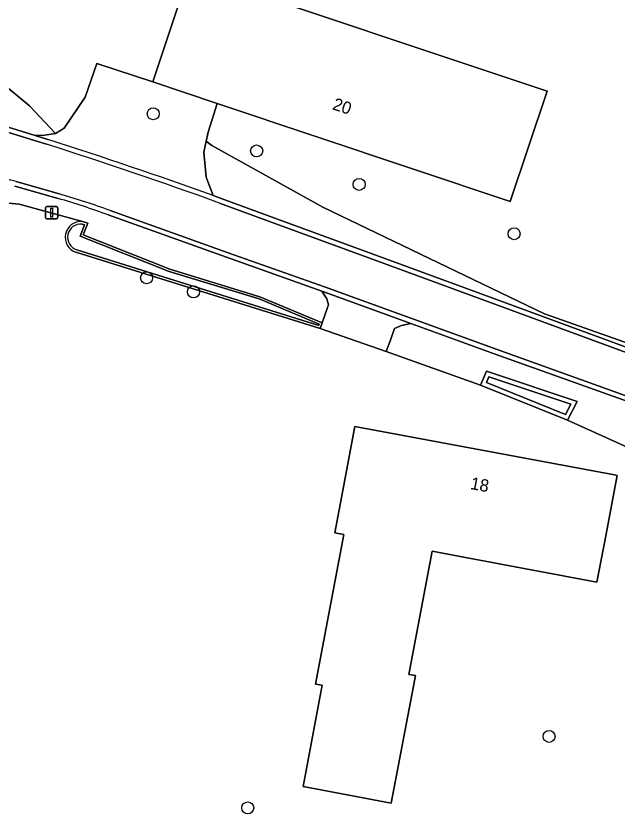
# Model space of a CAD drawing. Extents: x 162510 to 163918, y 388494 to 389774.
# Drawn here: x 162567.7 to 162616.6, y 389035.1 to 389100.2 of the extents above; entities that cross this region are included whole.
import ezdxf

# ---------------------------------------------------------------- set-up
doc = ezdxf.new("R2010")
doc.units = 0
for name, color, linetype in [('IMGEO_Berm_groen', 7, 'Continuous'), ('IMGEO_Boom', 7, 'Continuous'), ('IMGEO_Erf', 7, 'Continuous'), ('IMGEO_Groenvoorziening', 7, 'Continuous'), ('IMGEO_Oever', 7, 'Continuous'), ('IMGEO_Pand', 7, 'Continuous'), ('IMGEO_Pand_nummerreeks', 7, 'Continuous'), ('IMGEO_Rijbaan_lokaal_gesloten', 7, 'Continuous'), ('IMGEO_Rijbaan_lokaal_halfverhard', 7, 'Continuous'), ('IMGEO_Rijbaan_lokaal_open', 7, 'Continuous'), ('IMGEO_Verkeersbordpaal', 7, 'Continuous'), ('IMGEO_Voetpad_halfverhard', 7, 'Continuous'), ('IMGEO_Waterloop', 7, 'Continuous')]:
    doc.layers.add(name, color=color, linetype=linetype)

msp = doc.modelspace()

# ---------------------------------------------------------------- linework, layer by layer
at = {"layer": 'IMGEO_Berm_groen'}
for points in [[(162599.769, 389075.181), (162599.005, 389075.013), (162598.439, 389074.769), (162598.136, 389073.919), (162597.772, 389072.896), (162605.424, 389070.178), (162605.91, 389071.318), (162613.301, 389068.852), (162612.506, 389067.31), (162621.016, 389063.464), (162636.603, 389058.338), (162636.901, 389059.229), (162622.591, 389064.006)], [(162633.167, 389063.141), (162629.224, 389064.578), (162619.309, 389068.164), (162606.622, 389072.695), (162599.769, 389075.181)]]:
    msp.add_lwpolyline(points, dxfattribs=at)
at = {"layer": 'IMGEO_Boom'}
for centre in [(162578.829, 389092.237), (162587.236, 389089.214), (162595.566, 389086.496), (162608.163, 389082.483), (162578.292, 389078.903), (162582.101, 389077.76), (162611.002, 389041.609), (162586.511, 389035.793)]:
    msp.add_circle(centre, 0.489, dxfattribs=at)
at = {"layer": 'IMGEO_Erf'}
for points in [[(162557.496, 389100.727), (162561.475, 389097.699), (162566.874, 389094.459), (162568.765, 389092.878), (162570.879, 389090.626), (162571.596, 389091.063), (162573.303, 389093.589), (162574.241, 389096.331), (162578.784, 389094.826), (162581.781, 389103.795), (162610.841, 389094.076), (162607.844, 389085.107), (162584.039, 389093.069), (162583.288, 389090.735), (162583.138, 389090.012), (162583.595, 389089.671), (162592.606, 389084.643), (162610.637, 389075.969), (162619.919, 389072.683)], [(162573.072, 389083.47), (162567.934, 389084.89), (162565.92, 389085.075), (162565.003, 389085.162), (162560.951, 389085.473), (162557.784, 389085.129), (162557.523, 389080.69), (162560.632, 389000), (162561.923, 388970.136), (162563.311, 388929.674), (162563.923, 388911.946), (162569.898, 388915.03), (162570.179, 388926.053), (162598.167, 388927.269), (162614.582, 388927.982), (162666.94, 388930.257)], [(162677.463, 389048.046), (162644.844, 389055.627), (162639.858, 389057.267), (162636.603, 389058.338), (162621.016, 389063.464), (162612.506, 389067.31), (162605.424, 389070.178), (162597.772, 389072.896), (162592.401, 389074.784), (162572.538, 389080.978)]]:
    msp.add_lwpolyline(points, dxfattribs=at)
msp.add_lwpolyline([(162604.218, 389056.155), (162601.5, 389056.669), (162599.608, 389046.654), (162600.138, 389046.554), (162600.085, 389046.274), (162598.18, 389036.191), (162591.005, 389037.546), (162592.557, 389045.76), (162592.019, 389045.861), (162594.315, 389058.019), (162593.588, 389058.156), (162594.294, 389061.894), (162595.223, 389066.807), (162616.336, 389062.871), (162616.534, 389062.834), (162615.607, 389057.921), (162614.892, 389054.138)], close=True, dxfattribs=at)
msp.add_arc((162572.96, 389082.191), 1.284, 84.97508, 250.8354, dxfattribs=at)
at = {"layer": 'IMGEO_Groenvoorziening'}
for points in [[(162560.043, 389093.285), (162564.347, 389091.96), (162569.142, 389090.491), (162569.821, 389090.468), (162570.879, 389090.626), (162568.765, 389092.878), (162566.874, 389094.459), (162561.475, 389097.699)], [(162620.188, 389073.585), (162619.919, 389072.683), (162610.637, 389075.969), (162592.606, 389084.643), (162583.595, 389089.671), (162583.138, 389090.012), (162582.949, 389089.105), (162583.143, 389087.072), (162583.689, 389085.599), (162584.363, 389085.356), (162588.931, 389083.662), (162597.729, 389080.442), (162608.065, 389076.654), (162620.144, 389072.2), (162630.325, 389068.434)], [(162557.804, 389086.858), (162557.784, 389085.129), (162560.951, 389085.473), (162565.003, 389085.162), (162565.92, 389085.075), (162567.934, 389084.89), (162573.072, 389083.47), (162573.519, 389083.346), (162573.142, 389082.396), (162580.177, 389079.602), (162587.495, 389077.364), (162592.559, 389075.234), (162592.998, 389076.477), (162593.077, 389076.701), (162592.93, 389077.198), (162592.545, 389077.801), (162584.785, 389080.564), (162575.172, 389084.009)], [(162571.101, 389085.355), (162567.569, 389086.36)]]:
    msp.add_lwpolyline(points, dxfattribs=at)
msp.add_arc((162553.636, 389025.702), 62.157, 69.72791, 73.68109, dxfattribs=at)
at = {"layer": 'IMGEO_Oever'}
for points in [[(162573.045, 389083.274), (162573.256, 389083.215), (162572.887, 389082.286), (162580.112, 389079.417), (162587.428, 389077.179), (162592.313, 389075.125), (162592.279, 389075.028), (162572.607, 389081.162)], [(162580.177, 389079.602), (162573.142, 389082.396), (162573.519, 389083.346), (162573.072, 389083.47)], [(162572.538, 389080.978), (162592.401, 389074.784), (162592.559, 389075.234), (162587.495, 389077.364), (162580.177, 389079.602)]]:
    msp.add_lwpolyline(points, dxfattribs=at)
for points in [[(162605.91, 389071.318), (162605.424, 389070.178), (162612.506, 389067.31), (162613.301, 389068.852)], [(162606.12, 389070.852), (162612.766, 389068.634), (162612.329, 389067.787), (162605.92, 389070.383)]]:
    msp.add_lwpolyline(points, close=True, dxfattribs=at)
for centre, radius, start, end in [((162572.96, 389082.191), 1.284, 84.97508, 250.8354), ((162572.96, 389082.19), 1.087, 85.49441, 251.07303)]:
    msp.add_arc(centre, radius, start, end, dxfattribs=at)
at = {"layer": 'IMGEO_Pand'}
for points in [[(162578.784, 389094.826), (162584.039, 389093.069), (162607.844, 389085.107), (162610.841, 389094.076), (162581.781, 389103.795)], [(162604.218, 389056.155), (162614.892, 389054.138), (162615.607, 389057.921), (162616.534, 389062.834), (162616.336, 389062.871), (162595.223, 389066.807), (162594.294, 389061.894), (162593.588, 389058.156), (162594.315, 389058.019), (162592.019, 389045.861), (162592.557, 389045.76), (162591.005, 389037.546), (162598.18, 389036.191), (162600.085, 389046.274), (162600.138, 389046.554), (162599.608, 389046.654), (162601.5, 389056.669)]]:
    msp.add_lwpolyline(points, close=True, dxfattribs=at)
at = {"layer": 'IMGEO_Rijbaan_lokaal_gesloten'}
for points in [[(162570.141, 389089.767), (162564.229, 389091.578), (162559.938, 389092.899)], [(162567.675, 389086.732), (162571.175, 389085.726)], [(162630.186, 389068.059), (162619.847, 389071.883), (162607.927, 389076.278), (162597.591, 389080.066), (162588.792, 389083.287), (162584.227, 389084.98)], [(162575.34, 389084.366), (162584.931, 389080.923), (162592.748, 389078.167), (162606.773, 389073.076), (162619.448, 389068.517), (162629.327, 389064.949), (162633.3, 389063.513)]]:
    msp.add_lwpolyline(points, dxfattribs=at)
for centre, radius, start, end in [((162449.728, 388712.327), 396.182, 70.1543, 72.30597), ((162560.208, 389057.852), 29.83, 75.50391, 88.70383), ((162553.555, 389024.708), 63.511, 69.93984, 73.89327)]:
    msp.add_arc(centre, radius, start, end, dxfattribs=at)
at = {"layer": 'IMGEO_Rijbaan_lokaal_halfverhard'}
for points in [[(162570.258, 389090.149), (162569.142, 389090.491), (162564.347, 389091.96), (162560.043, 389093.285)], [(162559.938, 389092.899), (162564.229, 389091.578), (162570.141, 389089.767)], [(162571.175, 389085.726), (162567.675, 389086.732)], [(162567.569, 389086.36), (162571.101, 389085.355)], [(162630.325, 389068.434), (162620.144, 389072.2), (162608.065, 389076.654), (162597.729, 389080.442), (162588.931, 389083.662), (162584.363, 389085.356), (162583.689, 389085.599)], [(162584.227, 389084.98), (162588.792, 389083.287), (162597.591, 389080.066), (162607.927, 389076.278), (162619.847, 389071.883), (162630.186, 389068.059)], [(162575.172, 389084.009), (162584.785, 389080.564), (162592.545, 389077.801), (162592.692, 389077.749), (162599.769, 389075.181), (162606.622, 389072.695), (162619.309, 389068.164), (162629.224, 389064.578), (162633.167, 389063.141)], [(162633.3, 389063.513), (162629.327, 389064.949), (162619.448, 389068.517), (162606.773, 389073.076), (162592.748, 389078.167), (162584.931, 389080.923), (162575.34, 389084.366)]]:
    msp.add_lwpolyline(points, dxfattribs=at)
for centre, radius, start, end in [((162449.728, 388712.327), 396.182, 70.1543, 72.30597), ((162450.179, 388713.593), 395.238, 70.25732, 72.31315), ((162560.208, 389057.852), 29.83, 75.50391, 88.70383), ((162553.636, 389025.702), 62.157, 69.72791, 73.68109), ((162553.555, 389024.708), 63.511, 69.93984, 73.89327)]:
    msp.add_arc(centre, radius, start, end, dxfattribs=at)
at = {"layer": 'IMGEO_Rijbaan_lokaal_open'}
for points in [[(162583.288, 389090.735), (162584.039, 389093.069), (162578.784, 389094.826), (162574.241, 389096.331), (162573.303, 389093.589), (162571.596, 389091.063), (162570.879, 389090.626), (162569.821, 389090.468), (162569.142, 389090.491), (162570.258, 389090.149)], [(162583.689, 389085.599), (162583.143, 389087.072), (162582.949, 389089.105), (162583.138, 389090.012), (162583.288, 389090.735)]]:
    msp.add_lwpolyline(points, dxfattribs=at)
msp.add_arc((162450.179, 388713.593), 395.238, 70.25732, 72.31315, dxfattribs=at)
at = {"layer": 'IMGEO_Verkeersbordpaal'}
for p, q in [((162570.073, 389083.796), (162570.073, 389084.596)), ((162570.073, 389084.596), (162570.073, 389083.796)), ((162570.173, 389084.696), (162570.963, 389084.696)), ((162570.963, 389084.696), (162570.173, 389084.696)), ((162571.063, 389084.596), (162571.063, 389083.796)), ((162571.063, 389083.796), (162571.063, 389084.596)), ((162570.963, 389083.696), (162570.173, 389083.696)), ((162570.173, 389083.696), (162570.963, 389083.696))]:
    msp.add_line(p, q, dxfattribs=at)
msp.add_lwpolyline([(162570.493, 389084.571), (162570.643, 389084.571), (162570.643, 389083.821), (162570.493, 389083.821), (162570.493, 389084.571)], dxfattribs=at)
for centre, start, end in [((162570.173, 389084.596), 90, 180), ((162570.173, 389084.596), 90, 180), ((162570.963, 389084.596), 0, 90), ((162570.963, 389084.596), 360, 90), ((162570.173, 389083.796), 180, 270), ((162570.173, 389083.796), 180, 270), ((162570.963, 389083.796), 270, 0), ((162570.963, 389083.796), 270, 0)]:
    msp.add_arc(centre, 0.1, start, end, dxfattribs=at)
at = {"layer": 'IMGEO_Voetpad_halfverhard'}
msp.add_lwpolyline([(162592.545, 389077.801), (162592.93, 389077.198), (162593.077, 389076.701), (162592.998, 389076.477), (162592.559, 389075.234), (162592.401, 389074.784), (162597.772, 389072.896), (162598.136, 389073.919), (162598.439, 389074.769), (162599.005, 389075.013), (162599.769, 389075.181), (162592.692, 389077.749)], close=True, dxfattribs=at)
at = {"layer": 'IMGEO_Waterloop'}
msp.add_lwpolyline([(162572.607, 389081.162), (162592.279, 389075.028), (162592.313, 389075.125), (162587.428, 389077.179), (162580.112, 389079.417), (162572.887, 389082.286), (162573.256, 389083.215), (162573.045, 389083.274)], dxfattribs=at)
msp.add_lwpolyline([(162606.12, 389070.852), (162605.92, 389070.383), (162612.329, 389067.787), (162612.766, 389068.634)], close=True, dxfattribs=at)
msp.add_arc((162572.96, 389082.19), 1.087, 85.49441, 251.07303, dxfattribs=at)

# ---------------------------------------------------------------- texts
at = {"layer": 'IMGEO_Pand_nummerreeks'}
for s, rotation, p in [('20', 341.50769, (162593.332, 389092.617)), ('18', 349.44039, (162604.557, 389061.731))]:
    msp.add_text(s, height=1, rotation=rotation, dxfattribs=at).set_placement(p)

doc.saveas('drawing.dxf')
